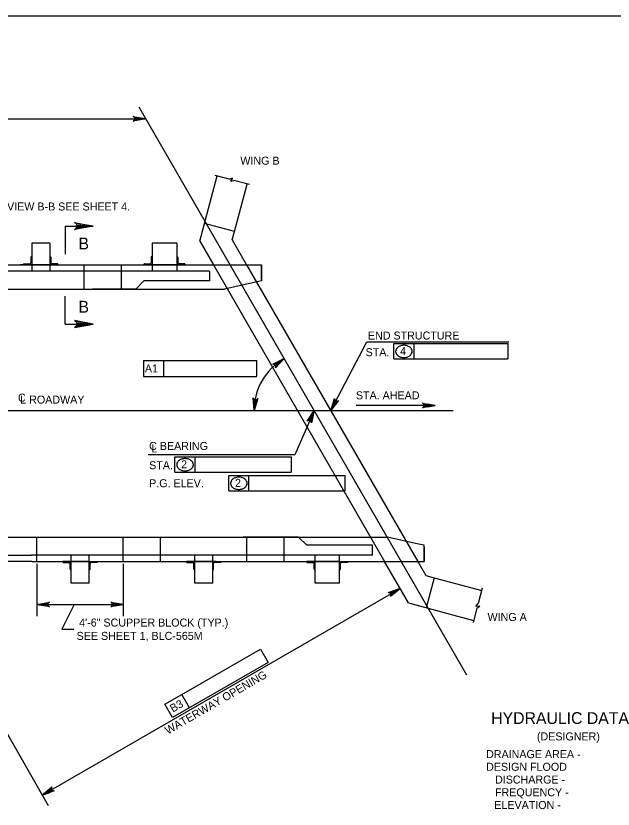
# Model space of a CAD drawing. Extents: x 638268 to 640277, y 295465 to 298435.
# Drawn here: x 638663 to 638887, y 296935.1 to 297232.5 of the extents above; entities that cross this region are included whole.
import ezdxf

# ---------------------------------------------------------------- set-up
doc = ezdxf.new("R2010")
doc.units = 0
for name, color, linetype in [('2', 7, 'Continuous'), ('3', 7, 'Continuous'), ('4', 7, 'Continuous')]:
    doc.layers.add(name, color=color, linetype=linetype)

msp = doc.modelspace()

# ---------------------------------------------------------------- linework, layer by layer
at = {"layer": '2'}
for p, q in [((638475.46, 297232.46), (639261.46, 297232.46)), ((638732.01, 297148.04), (638738.55, 297172.44)), ((638745.03, 297151.64), (638749.79, 297169.43)), ((638681.59, 297153.64), (638681.59, 297143.15)), ((638681.59, 297153.64), (638692.08, 297153.64)), ((638745.03, 297151.64), (638733.78, 297154.65)), ((638744.18, 297148.49), (638745.03, 297151.64)), ((638732.01, 297148.04), (638737.15, 297139.14)), ((638744.18, 297148.49), (638749.58, 297139.14)), ((638675.77, 297147.23), (638669.04, 297147.23)), ((638675.77, 297147.23), (638669.04, 297147.23)), ((638675.77, 297147.23), (638669.04, 297147.23)), ((638669.04, 297147.23), (638669.04, 297136.74)), ((638675.77, 297147.23), (638675.77, 297136.74)), ((638723.39, 297147.23), (638714.15, 297147.23)), ((638714.15, 297147.23), (638714.15, 297136.74)), ((638723.39, 297147.23), (638723.39, 297136.74)), ((638668.68, 297142.05), (638668.68, 297139.86)), ((638668.86, 297142.23), (638669.04, 297142.23)), ((638669.04, 297142.23), (638669.04, 297139.14)), ((638675.95, 297142.23), (638675.77, 297142.23)), ((638675.77, 297142.23), (638675.77, 297139.14)), ((638676.13, 297142.05), (638676.13, 297139.86)), ((638713.79, 297142.05), (638713.79, 297139.86)), ((638713.97, 297142.23), (638714.15, 297142.23)), ((638714.15, 297142.23), (638714.15, 297139.14)), ((638723.57, 297142.23), (638723.39, 297142.23)), ((638723.39, 297142.23), (638723.39, 297139.14)), ((638723.75, 297142.05), (638723.75, 297139.86)), ((638543.27, 297139.14), (638755.15, 297139.14)), ((638608.04, 297139.14), (638755.13, 297139.14)), ((638667.79, 297139.14), (638664.7, 297139.14)), ((638665.95, 297139.32), (638665.95, 297139.14)), ((638669.04, 297139.14), (638665.95, 297139.14)), ((638666.13, 297139.5), (638668.31, 297139.5)), ((638677.02, 297139.14), (638667.79, 297139.14)), ((638677.02, 297139.14), (638667.79, 297139.14)), ((638675.77, 297139.14), (638669.04, 297139.14)), ((638675.77, 297139.14), (638678.86, 297139.14)), ((638678.68, 297139.5), (638676.5, 297139.5)), ((638677.02, 297139.14), (638680.11, 297139.14)), ((638678.86, 297139.32), (638678.86, 297139.14)), ((638688.57, 297139.14), (638688.57, 297130.02)), ((638702.6, 297139.14), (638702.6, 297130.02)), ((638711.06, 297139.32), (638711.06, 297139.14)), ((638714.15, 297139.14), (638711.06, 297139.14)), ((638711.24, 297139.5), (638713.42, 297139.5)), ((638723.39, 297139.14), (638714.15, 297139.14)), ((638723.39, 297139.14), (638726.48, 297139.14)), ((638726.3, 297139.5), (638724.11, 297139.5)), ((638726.48, 297139.32), (638726.48, 297139.14)), ((638737.15, 297139.14), (638801.34, 297027.96)), ((638749.58, 297139.14), (638813.77, 297027.96)), ((638755.13, 297133.76), (638755.13, 297139.14)), ((638755.13, 297139.14), (638755.13, 297133.11)), ((638755.15, 297133.75), (638755.15, 297139.14)), ((638735.71, 297136.74), (638607.87, 297136.74)), ((638735.71, 297136.74), (638735.71, 297133.11)), ((638707.98, 297130.02), (638711.07, 297133.11)), ((638735.71, 297133.11), (638711.07, 297133.11)), ((638752.96, 297132.62), (638741.28, 297130.02)), ((638755.13, 297133.11), (638752.96, 297132.62)), ((638590.42, 297130.02), (638741.28, 297130.02)), ((638707.98, 297130.02), (638691.82, 297130.02)), ((638681.59, 297116.91), (638681.59, 297127.39)), ((638681.59, 297116.91), (638692.08, 297116.91)), ((638651.51, 297037.09), (638667.67, 297037.09)), ((638651.51, 297037.09), (638802.37, 297037.09)), ((638670.96, 297027.96), (638670.96, 297037.09)), ((638703.3, 297027.96), (638703.3, 297037.09)), ((638717.32, 297027.96), (638717.32, 297037.09)), ((638769.07, 297037.09), (638748.29, 297037.09)), ((638749.66, 297027.96), (638749.66, 297037.09)), ((638763.69, 297027.96), (638763.69, 297037.09)), ((638769.07, 297037.09), (638772.16, 297033.99)), ((638814.05, 297034.48), (638802.37, 297037.09)), ((638816.22, 297033.99), (638814.05, 297034.48)), ((638796.8, 297033.99), (638772.16, 297033.99)), ((638796.8, 297030.36), (638796.8, 297033.99)), ((638816.22, 297027.96), (638816.22, 297033.99)), ((638816.22, 297033.35), (638816.22, 297027.96)), ((638623.78, 297030.36), (638668.96, 297030.36)), ((638796.8, 297030.36), (638668.96, 297030.36)), ((638683.77, 297019.87), (638683.77, 297030.36)), ((638690.49, 297019.87), (638690.49, 297030.36)), ((638730.13, 297019.87), (638730.13, 297030.36)), ((638736.86, 297019.87), (638736.86, 297030.36)), ((638775.24, 297019.87), (638775.24, 297030.36)), ((638784.48, 297019.87), (638784.48, 297030.36)), ((638669.05, 297027.96), (638645.34, 297027.96)), ((638669.13, 297027.96), (638816.22, 297027.96)), ((638680.68, 297027.78), (638680.68, 297027.96)), ((638683.77, 297027.96), (638680.68, 297027.96)), ((638680.86, 297027.6), (638683.04, 297027.6)), ((638683.4, 297025.06), (638683.4, 297027.24)), ((638690.49, 297027.96), (638683.77, 297027.96)), ((638683.77, 297024.87), (638683.77, 297027.96)), ((638690.49, 297024.87), (638690.49, 297027.96)), ((638690.49, 297027.96), (638693.59, 297027.96)), ((638690.86, 297025.06), (638690.86, 297027.24)), ((638693.4, 297027.6), (638691.22, 297027.6)), ((638693.59, 297027.78), (638693.59, 297027.96)), ((638727.04, 297027.78), (638727.04, 297027.96)), ((638730.13, 297027.96), (638727.04, 297027.96)), ((638727.22, 297027.6), (638729.4, 297027.6)), ((638738.11, 297027.96), (638728.88, 297027.96)), ((638729.77, 297025.06), (638729.77, 297027.24)), ((638736.86, 297027.96), (638730.13, 297027.96)), ((638730.13, 297024.87), (638730.13, 297027.96)), ((638736.86, 297024.87), (638736.86, 297027.96)), ((638736.86, 297027.96), (638739.95, 297027.96)), ((638737.22, 297025.06), (638737.22, 297027.24)), ((638739.77, 297027.6), (638737.59, 297027.6)), ((638739.95, 297027.78), (638739.95, 297027.96)), ((638772.15, 297027.78), (638772.15, 297027.96)), ((638775.24, 297027.96), (638772.15, 297027.96)), ((638772.33, 297027.6), (638774.51, 297027.6)), ((638774.88, 297025.06), (638774.88, 297027.24)), ((638784.48, 297027.96), (638775.24, 297027.96)), ((638775.24, 297024.87), (638775.24, 297027.96)), ((638784.48, 297024.87), (638784.48, 297027.96)), ((638784.48, 297027.96), (638787.57, 297027.96)), ((638784.84, 297025.06), (638784.84, 297027.24)), ((638787.39, 297027.6), (638785.2, 297027.6)), ((638787.57, 297027.78), (638787.57, 297027.96)), ((638810.32, 297012.39), (638801.34, 297027.96)), ((638813.77, 297027.96), (638816.8, 297022.71)), ((638683.59, 297024.87), (638683.77, 297024.87)), ((638690.68, 297024.87), (638690.49, 297024.87)), ((638729.95, 297024.87), (638730.13, 297024.87)), ((638737.04, 297024.87), (638736.86, 297024.87)), ((638775.06, 297024.87), (638775.24, 297024.87)), ((638784.66, 297024.87), (638784.48, 297024.87)), ((638816.8, 297022.71), (638819.95, 297021.86)), ((638690.49, 297019.87), (638683.77, 297019.87)), ((638736.86, 297019.87), (638730.13, 297019.87)), ((638736.86, 297019.87), (638730.13, 297019.87)), ((638784.48, 297019.87), (638775.24, 297019.87)), ((638819.95, 297021.86), (638816.94, 297010.62)), ((638819.95, 297021.86), (638837.74, 297017.1)), ((638810.32, 297012.39), (638834.73, 297005.85))]:
    msp.add_line(p, q, dxfattribs=at)
for points in [[(638692.08, 297153.64), (638685.09, 297152.33), (638685.62, 297152.7), (638685.9, 297153.17), (638685.98, 297153.64), (638685.9, 297154.11), (638685.62, 297154.58), (638685.09, 297154.95), (638692.08, 297153.64), (638685.62, 297154.58), (638685.9, 297154.11), (638692.08, 297153.64), (638685.98, 297153.64), (638685.9, 297153.17), (638692.08, 297153.64), (638685.62, 297152.7)], [(638692.08, 297116.91), (638685.09, 297118.22), (638685.62, 297117.85), (638685.9, 297117.38), (638685.98, 297116.91), (638685.9, 297116.44), (638685.62, 297115.97), (638685.09, 297115.6), (638692.08, 297116.91), (638685.62, 297115.97), (638685.9, 297116.44), (638692.08, 297116.91), (638685.98, 297116.91), (638685.9, 297117.38), (638692.08, 297116.91), (638685.62, 297117.85)]]:
    msp.add_lwpolyline(points, dxfattribs=at)
for centre, radius, start, end in [((638668.86, 297142.05), 0.182, 90, 179.9984), ((638675.95, 297142.05), 0.182, 0.0016, 90), ((638713.97, 297142.05), 0.182, 90, 179.9984), ((638723.57, 297142.05), 0.182, 0.0016, 90), ((638666.13, 297139.32), 0.182, 90, 179.9984), ((638668.31, 297139.86), 0.364, 270, 359.9984), ((638676.5, 297139.86), 0.364, 180.0016, 270), ((638678.68, 297139.32), 0.182, 0.0016, 90), ((638711.24, 297139.32), 0.182, 90, 179.9984), ((638713.42, 297139.86), 0.364, 270, 359.9984), ((638724.11, 297139.86), 0.364, 180.0016, 270), ((638726.3, 297139.32), 0.182, 0.0016, 90), ((638680.86, 297027.78), 0.182, 180.0016, 270), ((638683.04, 297027.24), 0.364, 0.0016, 90), ((638691.22, 297027.24), 0.364, 90, 179.9984), ((638693.4, 297027.78), 0.182, 270, 359.9984), ((638727.22, 297027.78), 0.182, 180.0016, 270), ((638729.4, 297027.24), 0.364, 0.0016, 90), ((638737.59, 297027.24), 0.364, 90, 179.9984), ((638739.77, 297027.78), 0.182, 270, 359.9984), ((638772.33, 297027.78), 0.182, 180.0016, 270), ((638774.51, 297027.24), 0.364, 0.0016, 90), ((638785.2, 297027.24), 0.364, 90, 179.9984), ((638787.39, 297027.78), 0.182, 270, 359.9984), ((638683.59, 297025.06), 0.182, 180.0016, 270), ((638690.68, 297025.06), 0.182, 270, 359.9984), ((638729.95, 297025.06), 0.182, 180.0016, 270), ((638737.04, 297025.06), 0.182, 270, 359.9984), ((638775.06, 297025.06), 0.182, 180.0016, 270), ((638784.66, 297025.06), 0.182, 270, 359.9984)]:
    msp.add_arc(centre, radius, start, end, dxfattribs=at)
at = {"layer": '3'}
for p, q in [((638709.2, 297198.31), (638832.07, 296985.5)), ((638743.09, 297171.22), (638737.75, 297172.65)), ((638743.09, 297171.22), (638744.35, 297171.76)), ((638744.35, 297171.76), (638743.49, 297170.46)), ((638743.49, 297170.46), (638744.83, 297170.76)), ((638750.66, 297169.19), (638744.83, 297170.76)), ((638837.97, 297017.96), (638836.41, 297012.13)), ((638835.49, 297011.12), (638836.41, 297012.13)), ((638837.04, 297011.21), (638835.49, 297011.12)), ((638835.95, 297010.4), (638837.04, 297011.21)), ((638835.95, 297010.4), (638834.52, 297005.06))]:
    msp.add_line(p, q, dxfattribs=at)
at = {"layer": '4'}
for p, q in [((638520.34, 297193.9), (638711.75, 297193.9)), ((638781.12, 297084.5), (638794.7, 297110.22)), ((638794.7, 297110.22), (638847.88, 297110.22)), ((638804.8, 297109.61), (638812.38, 297109.61)), ((638804.8, 297103.84), (638804.8, 297109.61)), ((638812.38, 297103.84), (638812.38, 297109.61)), ((638812.38, 297109.61), (638847.56, 297109.61)), ((638847.56, 297109.61), (638847.56, 297103.84)), ((638710.94, 297103.23), (638710.93, 297097.33)), ((638710.94, 297103.23), (638718.5, 297103.23)), ((638718.49, 297097.33), (638718.5, 297103.23)), ((638718.5, 297103.23), (638753.46, 297103.23)), ((638753.45, 297097.33), (638753.46, 297103.23)), ((638804.8, 297103.84), (638847.56, 297103.84)), ((638710.93, 297097.33), (638753.45, 297097.33)), ((638817.36, 297086.44), (638790.72, 297086.44)), ((638541.99, 297084.5), (638827.01, 297084.5)), ((638774.91, 297084.5), (638767.73, 297067.9)), ((638767.73, 297067.9), (638712.65, 297067.9)), ((638722.7, 297067.14), (638730.28, 297067.14)), ((638722.7, 297061.37), (638722.7, 297067.14)), ((638730.28, 297061.37), (638730.28, 297067.14)), ((638730.28, 297067.14), (638766.29, 297067.14)), ((638766.29, 297067.14), (638766.29, 297061.37)), ((638722.7, 297061.37), (638766.29, 297061.37)), ((638742.89, 297054.4), (638742.89, 297060.17)), ((638742.89, 297060.17), (638750.47, 297060.17)), ((638750.47, 297054.4), (638750.47, 297060.17)), ((638750.47, 297060.17), (638786.48, 297060.17)), ((638786.48, 297060.17), (638786.48, 297054.4)), ((638742.89, 297054.4), (638786.48, 297054.4)), ((638670.96, 297027.03), (638670.96, 297007.4)), ((638703.3, 297027.03), (638703.3, 297007.4)), ((638628.28, 297017.71), (638675.2, 296936.44)), ((638672.95, 296940.33), (638807.18, 297017.83)), ((638670.96, 297011.83), (638703.3, 297011.83)), ((638684.92, 297011.83), (638680.33, 297002.6)), ((638680.33, 297002.6), (638684.76, 297002.6)), ((638725.27, 296978.09), (638754.85, 296995.13)), ((638754.85, 296995.13), (638757.73, 296990.13)), ((638757.73, 296990.13), (638721.75, 296969.41)), ((638718.87, 296974.4), (638725.27, 296978.09)), ((638728.15, 296973.09), (638725.27, 296978.09)), ((638721.75, 296969.41), (638718.87, 296974.4))]:
    msp.add_line(p, q, dxfattribs=at)
for points in [[(638711.75, 297193.9), (638707.09, 297193.02), (638707.45, 297193.27), (638707.63, 297193.58), (638707.69, 297193.9), (638707.63, 297194.21), (638707.45, 297194.52), (638707.09, 297194.77), (638711.75, 297193.9), (638707.45, 297194.52), (638707.63, 297194.21), (638711.75, 297193.9), (638707.69, 297193.9), (638707.63, 297193.58), (638711.75, 297193.9), (638707.45, 297193.27)], [(638763.64, 297104.02), (638760.46, 297100.5), (638760.6, 297100.91), (638760.56, 297101.27), (638760.41, 297101.56), (638760.18, 297101.77), (638759.84, 297101.91), (638759.4, 297101.89), (638763.64, 297104.02), (638759.84, 297101.91), (638760.18, 297101.77), (638763.64, 297104.02), (638760.41, 297101.56), (638760.56, 297101.27), (638763.64, 297104.02), (638760.6, 297100.91)], [(638752.37, 297084.49), (638752.07, 297089.22), (638752.27, 297088.84), (638752.56, 297088.61), (638752.87, 297088.52), (638753.18, 297088.54), (638753.52, 297088.68), (638753.81, 297089.01), (638752.37, 297084.49), (638753.52, 297088.68), (638753.18, 297088.54), (638752.37, 297084.49), (638752.87, 297088.52), (638752.56, 297088.61), (638752.37, 297084.49), (638752.27, 297088.84)], [(638781.12, 297084.5), (638782.52, 297089.03), (638782.58, 297088.6), (638782.77, 297088.29), (638783.02, 297088.1), (638783.32, 297088), (638783.68, 297088.02), (638784.07, 297088.22), (638781.12, 297084.5), (638783.68, 297088.02), (638783.32, 297088), (638781.12, 297084.5), (638783.02, 297088.1), (638782.77, 297088.29), (638781.12, 297084.5), (638782.58, 297088.6)], [(638820.24, 297086.44), (638815.58, 297085.56), (638815.94, 297085.81), (638816.12, 297086.12), (638816.18, 297086.44), (638816.12, 297086.75), (638815.94, 297087.06), (638815.58, 297087.31), (638820.24, 297086.44), (638815.94, 297087.06), (638816.12, 297086.75), (638820.24, 297086.44), (638816.18, 297086.44), (638816.12, 297086.12), (638820.24, 297086.44), (638815.94, 297085.81)], [(638774.91, 297084.5), (638773.86, 297079.88), (638773.77, 297080.31), (638773.56, 297080.6), (638773.29, 297080.77), (638772.99, 297080.85), (638772.62, 297080.8), (638772.25, 297080.57), (638774.91, 297084.5), (638772.62, 297080.8), (638772.99, 297080.85), (638774.91, 297084.5), (638773.29, 297080.77), (638773.56, 297080.6), (638774.91, 297084.5), (638773.77, 297080.31)], [(638807.18, 297017.83), (638803.58, 297014.75), (638803.77, 297015.14), (638803.77, 297015.5), (638803.66, 297015.8), (638803.46, 297016.05), (638803.15, 297016.22), (638802.71, 297016.26), (638807.18, 297017.83), (638803.15, 297016.22), (638803.46, 297016.05), (638807.18, 297017.83), (638803.66, 297015.8), (638803.77, 297015.5), (638807.18, 297017.83), (638803.77, 297015.14)], [(638670.96, 297011.83), (638675.62, 297012.7), (638675.26, 297012.45), (638675.08, 297012.14), (638675.02, 297011.83), (638675.08, 297011.51), (638675.26, 297011.2), (638675.62, 297010.95), (638670.96, 297011.83), (638675.26, 297011.2), (638675.08, 297011.51), (638670.96, 297011.83), (638675.02, 297011.83), (638675.08, 297012.14), (638670.96, 297011.83), (638675.26, 297012.45)], [(638703.3, 297011.83), (638698.64, 297010.95), (638699, 297011.2), (638699.18, 297011.51), (638699.24, 297011.83), (638699.18, 297012.14), (638699, 297012.45), (638698.64, 297012.7), (638703.3, 297011.83), (638699, 297012.45), (638699.18, 297012.14), (638703.3, 297011.83), (638699.24, 297011.83), (638699.18, 297011.51), (638703.3, 297011.83), (638699, 297011.2)], [(638672.95, 296940.33), (638676.55, 296943.42), (638676.36, 296943.02), (638676.36, 296942.66), (638676.47, 296942.36), (638676.67, 296942.12), (638676.99, 296941.94), (638677.42, 296941.91), (638672.95, 296940.33), (638676.99, 296941.94), (638676.67, 296942.12), (638672.95, 296940.33), (638676.47, 296942.36), (638676.36, 296942.66), (638672.95, 296940.33), (638676.36, 296943.02)]]:
    msp.add_lwpolyline(points, dxfattribs=at)
for points in [[(638817.36, 297086.92), (638817.36, 297085.96), (638820.24, 297086.44)], [(638774.19, 297081.6), (638773.28, 297081.99), (638774.91, 297084.5)], [(638804.34, 297016.77), (638804.84, 297015.9), (638807.18, 297017.83)], [(638673.92, 297012.32), (638673.92, 297011.33), (638670.96, 297011.83)], [(638700.35, 297012.32), (638700.35, 297011.33), (638703.3, 297011.83)], [(638675.3, 296942.27), (638675.8, 296941.4), (638672.95, 296940.33)], [(638675.8, 296941.4), (638675.3, 296942.27), (638672.95, 296940.33)]]:
    msp.add_lwpolyline(points, close=True, dxfattribs=at)
for centre, radius, start, end in [((638808.58, 297104.75), 4.22, 90, 106.9552), ((638808.58, 297104.75), 4.22, 73.0448, 90), ((638807.18, 297106.68), 1.71, 150.6308, 180), ((638807.18, 297106.68), 1.71, 180, 209.3692), ((638807.85, 297106.29), 2.49, 126.3544, 150.6308), ((638807.85, 297107.06), 2.49, 209.3692, 233.6456), ((638808.29, 297105.69), 3.23, 106.9552, 126.3544), ((638808.87, 297105.69), 3.23, 53.6456, 73.0448), ((638809.31, 297106.29), 2.49, 29.3692, 53.6456), ((638809.31, 297107.06), 2.49, 306.3544, 330.6308), ((638809.99, 297106.68), 1.71, 0, 29.3692), ((638809.99, 297106.68), 1.71, 330.6308, 0), ((638774.91, 297084.5), 22.54, 119.9992, 179.9979), ((638808.29, 297107.66), 3.23, 233.6456, 253.0448), ((638808.58, 297108.6), 4.22, 253.0448, 270), ((638808.58, 297108.6), 4.22, 270, 286.9552), ((638808.87, 297107.66), 3.23, 286.9552, 306.3544), ((638725.08, 297064.21), 1.71, 150.6308, 180), ((638725.08, 297064.21), 1.71, 180, 209.3692), ((638725.76, 297063.83), 2.49, 126.3544, 150.6308), ((638726.2, 297063.23), 3.23, 106.9552, 126.3544), ((638726.49, 297062.28), 4.22, 90, 106.9552), ((638726.49, 297062.28), 4.22, 73.0448, 90), ((638726.78, 297063.23), 3.23, 53.6456, 73.0448), ((638727.22, 297063.83), 2.49, 29.3692, 53.6456), ((638727.9, 297064.21), 1.71, 0, 29.3692), ((638727.9, 297064.21), 1.71, 330.6308, 0), ((638725.76, 297064.59), 2.49, 209.3692, 233.6456), ((638726.2, 297065.19), 3.23, 233.6456, 253.0448), ((638726.49, 297066.13), 4.22, 253.0448, 270), ((638726.49, 297066.13), 4.22, 270, 286.9552), ((638726.78, 297065.19), 3.23, 286.9552, 306.3544), ((638727.22, 297064.59), 2.49, 306.3544, 330.6308), ((638745.95, 297056.86), 2.49, 126.3544, 150.6308), ((638746.39, 297056.26), 3.23, 106.9552, 126.3544), ((638746.68, 297055.31), 4.22, 90, 106.9552), ((638746.68, 297055.31), 4.22, 73.0448, 90), ((638746.97, 297056.26), 3.23, 53.6456, 73.0448), ((638747.41, 297056.86), 2.49, 29.3692, 53.6456), ((638745.27, 297057.24), 1.71, 150.6308, 180), ((638745.27, 297057.24), 1.71, 180, 209.3692), ((638745.95, 297057.62), 2.49, 209.3692, 233.6456), ((638746.39, 297058.22), 3.23, 233.6456, 253.0448), ((638746.97, 297058.22), 3.23, 286.9552, 306.3544), ((638747.41, 297057.62), 2.49, 306.3544, 330.6308), ((638748.08, 297057.24), 1.71, 0, 29.3692), ((638748.08, 297057.24), 1.71, 330.6308, 0), ((638746.68, 297059.17), 4.22, 253.0448, 270), ((638746.68, 297059.17), 4.22, 270, 286.9552)]:
    msp.add_arc(centre, radius, start, end, dxfattribs=at)

# ---------------------------------------------------------------- texts
for s, height, p in [('WING B', 3, (638747.23, 297176.69)), ('FOR VIEW B-B SEE SHEET 4.', 3, (638650.17, 297159.5)), ('B', 4.43, (638686.53, 297121.21)), ('END STRUCTURE', 3, (638795.08, 297111.13)), ('STA.', 3, (638794.21, 297104.89)), ('4', 3, (638807.13, 297105.32)), ('STA. AHEAD', 3, (638790.57, 297088.72)), ('C', 3, (638663.83, 297087.85)), ('L ROADWAY', 3, (638664.69, 297087.11)), ('C BEARING', 3, (638713.03, 297069.74)), ('L', 3, (638713.86, 297068.83)), ('STA.', 3, (638713.03, 297062.51)), ('2', 3, (638725.04, 297062.86)), ('P.G. ELEV.', 3, (638713.03, 297055.76)), ('2', 3, (638745.23, 297055.89)), ('WING A', 3, (638839.94, 297005.63)), ('4\'-6" SCUPPER BLOCK (TYP.)', 3, (638686.79, 297003.54)), ('SEE SHEET 1, BLC-565M', 3, (638685.83, 296998.55)), ('HYDRAULIC DATA', 4.4292, (638841.31, 296967.02)), ('(DESIGNER)', 3, (638858.45, 296960.86)), ('DRAINAGE AREA - ', 3, (638839.39, 296954.22)), ('DESIGN FLOOD  ', 3, (638839.39, 296949.48)), ('   DISCHARGE - ', 3, (638839.39, 296944.69)), ('   FREQUENCY - ', 3, (638839.39, 296939.92)), ('   ELEVATION - ', 3, (638839.12, 296935.15))]:
    msp.add_text(s, height=height, dxfattribs=at).set_placement(p)
for s, height, rotation, p in [('B', 4.43, 360, (638686.53, 297144.91)), ('A1', 3, 359.9382, (638711.45, 297098.78)), ('WATERWAY OPENING', 3, 30, (638720.09, 296963.01)), ('B3', 3, 29.9438, (638721.92, 296971.26))]:
    msp.add_text(s, height=height, rotation=rotation, dxfattribs=at).set_placement(p)

doc.saveas('drawing.dxf')
